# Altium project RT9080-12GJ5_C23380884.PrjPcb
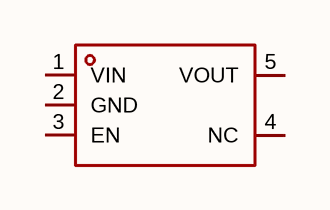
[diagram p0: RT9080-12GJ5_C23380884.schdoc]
1 sheet, 1 parts. Net scope: global (net labels, ports and power ports of the same name join across sheets).

## Sheet RT9080-12GJ5_C23380884.schdoc
size 127 x 101 mm

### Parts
U?  rt9080-12gj5_c23380884  [SOT-23-5_L2.9-W1.6-P0.95-LS2.8-BR]  (value not drawn)

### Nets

Not connected (* = marked no-connect by the designer): U? 1(VIN) 2(GND) 3(EN) 4(NC) 5(VOUT)

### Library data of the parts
U? = rt9080-12gj5_c23380884: 输出极性:正极;工作电压:5.5V;输出电压:1.2V;输出电流:600mA;电源纹波抑制比(PSRR):75dB@(1kHz);输出类型:固定;; Manufacturer: TECH PUBLIC(台舟); AddInBom: yes; ModelId: 7ba65df16e7b4570af156e925f9c37fe; ModelTransform: 114.173,114.173,0,90,0,0,0,0,0; Output Configuration: 正极; Voltage - Supply: 5.5V; Output Voltage: 1.2V; Output Current: 600mA; Voltage Dropout: 800mV@(600mA); standby current: 2uA; Noise: 50uVrms; Output Type: 固定; Number of Outputs: 1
